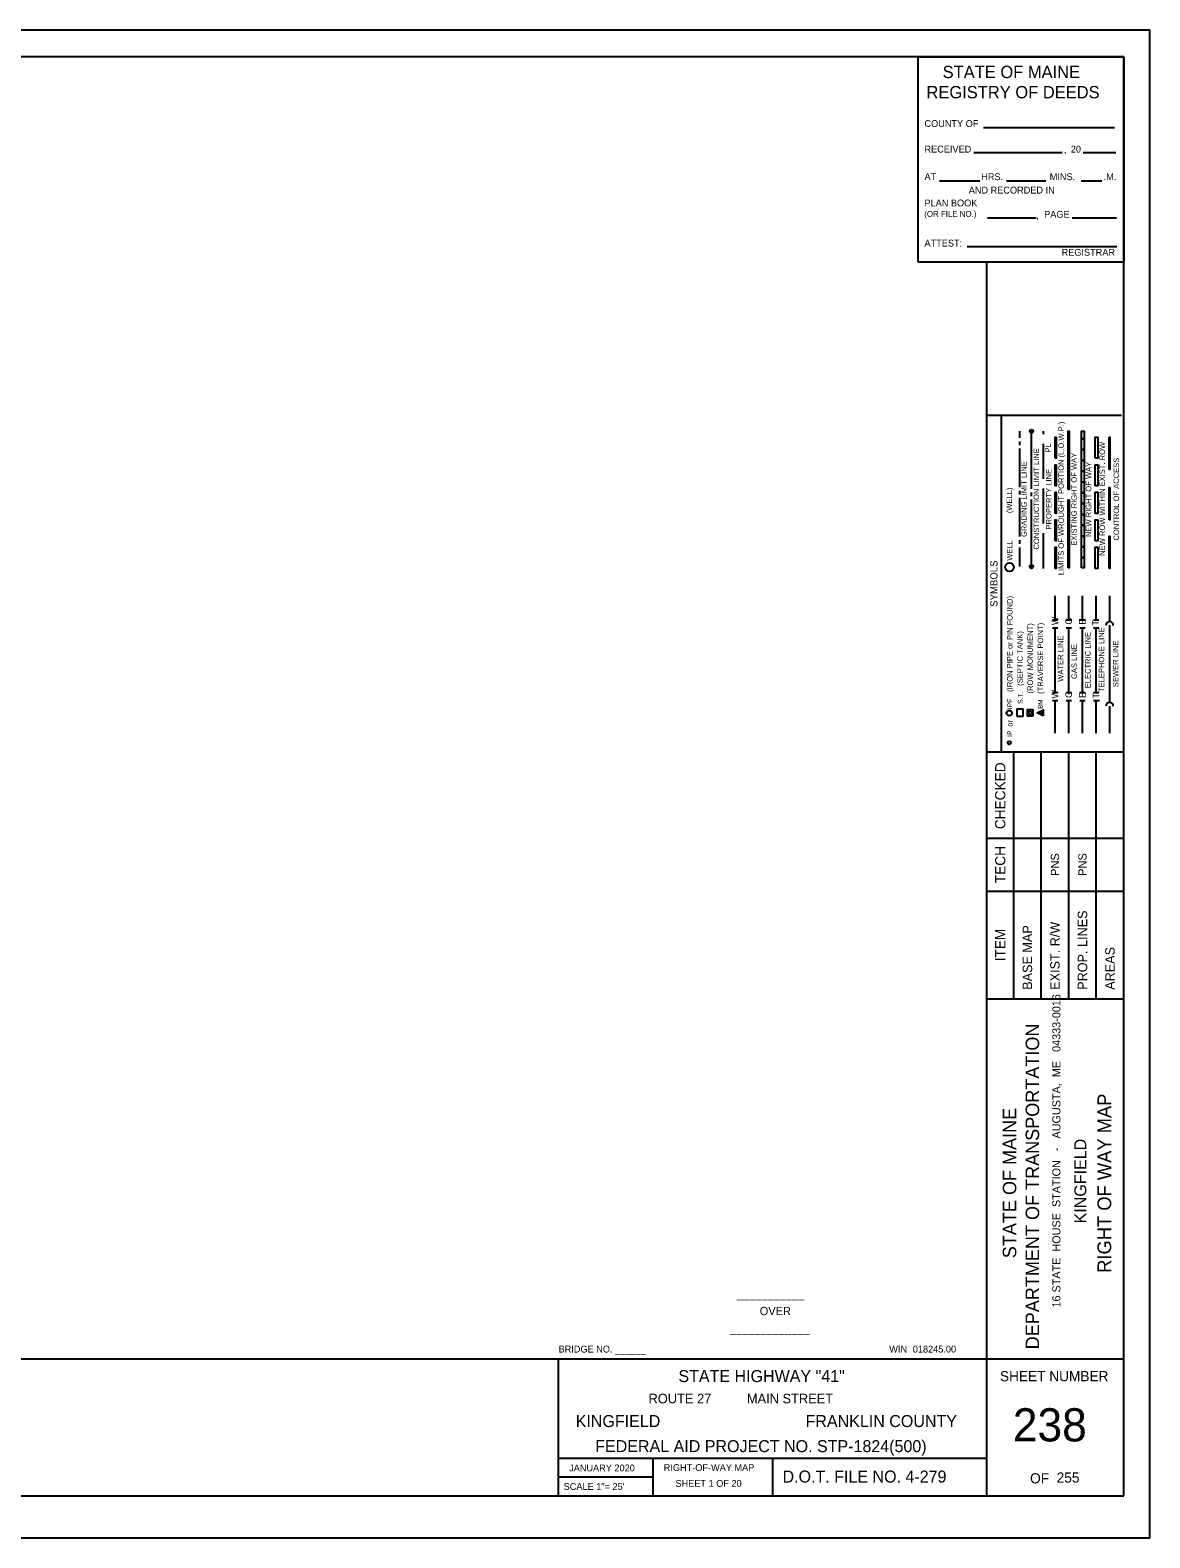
# Model space of a CAD drawing. Extents: x -415 to 435, y -303 to 247.
# Drawn here: x 26 to 435, y -303 to 247 of the extents above; entities that cross this region are included whole.
import ezdxf

# ---------------------------------------------------------------- set-up
doc = ezdxf.new("R2010")
doc.units = 0
for name, color, linetype in [('Border', 7, 'Continuous'), ('BRIDGE_TITLE', 7, 'Continuous'), ('HIGHWAY_TITLE', 7, 'Continuous'), ('PLOT BOUNDARY', 7, 'Continuous'), ('PRPTY SETUPS', 7, 'Continuous')]:
    doc.layers.add(name, color=color, linetype=linetype)

msp = doc.modelspace()

# ---------------------------------------------------------------- linework, layer by layer
at = {"layer": 'Border'}
for p, q in [((425, 237.5), (-375, 237.5)), ((425, -287.49), (425, 237.5)), ((375, -287.5), (375, 162.52)), ((375, 106.81), (424.21, 106.81)), ((380.25, 106.81), (380.25, -16.1)), ((387.03, 98.49), (387.03, 100.86)), ((391.35, 79.88), (391.35, 100.24)), ((395.67, 99.88), (395.67, 100.86)), ((387.03, 95.86), (387.03, 97.18)), ((387.03, 87.51), (387.03, 94.55)), ((395.67, 83.54), (395.67, 96.34)), ((387.03, 80.47), (387.03, 87.51)), ((387.03, 77.85), (387.03, 79.16)), ((391.35, 77.25), (391.35, 78.57)), ((395.67, 67.2), (395.67, 80)), ((387.03, 69.5), (387.03, 76.54)), ((391.35, 52.11), (391.35, 75.94)), ((387.03, 62.46), (387.03, 69.5)), ((387.03, 59.84), (387.03, 61.15)), ((395.67, 50.86), (395.67, 63.66)), ((387.03, 51.49), (387.03, 58.53)), ((399.99, 32.13), (399.99, 40.79)), ((404.97, 32.13), (404.97, 40.79)), ((409.94, 32.13), (409.94, 40.79)), ((414.92, 32.13), (414.92, 40.79)), ((419.9, 31.54), (419.9, 40.79)), ((399.01, 32.13), (400.98, 32.13)), ((399.01, 29.18), (400.98, 29.18)), ((399.99, 5.56), (399.99, 29.18)), ((403.98, 32.13), (405.95, 32.13)), ((403.98, 29.18), (405.95, 29.18)), ((404.97, 17.37), (404.97, 29.18)), ((408.96, 32.13), (410.93, 32.13)), ((408.96, 29.18), (410.93, 29.18)), ((409.94, 17.37), (409.94, 29.18)), ((413.94, 32.13), (415.9, 32.13)), ((413.94, 29.18), (415.9, 29.18)), ((414.92, 17.37), (414.92, 29.18)), ((419.9, 20.32), (419.9, 30.16)), ((404.97, 5.56), (404.97, 17.37)), ((409.94, 5.56), (409.94, 17.37)), ((414.92, 5.56), (414.92, 17.37)), ((419.9, 2.01), (419.9, 20.32)), ((399.01, 5.56), (400.98, 5.56)), ((403.98, 5.56), (405.95, 5.56)), ((408.96, 5.56), (410.93, 5.56)), ((413.94, 5.56), (415.9, 5.56)), ((399.01, 2.61), (400.98, 2.61)), ((399.99, -9.21), (399.99, 2.61)), ((403.98, 2.61), (405.95, 2.61)), ((404.97, -9.21), (404.97, 2.61)), ((408.96, 2.61), (410.93, 2.61)), ((409.94, -9.21), (409.94, 2.61)), ((413.94, 2.61), (416.1, 2.61)), ((414.92, -9.21), (414.92, 2.61)), ((419.9, -9.21), (419.9, 0.64)), ((375, -16.1), (425, -16.1)), ((384.84, -106.22), (384.84, -16.1)), ((394.88, -106.22), (394.88, -16.1)), ((404.92, -106.22), (404.92, -16.1)), ((414.96, -106.22), (414.96, -16.1)), ((375, -47.6), (425, -47.6)), ((375, -66.94), (425, -66.94)), ((375, -106.22), (425, -106.22)), ((-375, -237.49), (425, -237.49)), ((218.75, -287.5), (218.75, -237.49)), ((218.75, -273.75), (375, -273.75)), ((253.12, -273.75), (253.12, -287.5)), ((296.87, -273.75), (296.87, -287.5)), ((253.12, -280.62), (218.75, -280.62)), ((-375, -287.5), (425, -287.5))]:
    msp.add_line(p, q, dxfattribs=at)
for points in [[(404.71, 79.6), (404.71, 100.86), (405.1, 100.86), (405.1, 79.6)], [(409.62, 98.11), (409.62, 100.86), (410.6, 100.86), (410.6, 98.11)], [(399.99, 91.02), (399.99, 98.7), (400.39, 98.7), (400.39, 91.02)], [(409.62, 94.17), (409.62, 98.11), (410.6, 98.11), (410.6, 94.17)], [(409.62, 90.23), (409.62, 94.17), (410.6, 94.17), (410.6, 90.23)], [(414.59, 91.02), (414.59, 98.7), (415.58, 98.7), (415.58, 91.02)], [(419.7, 86.89), (419.7, 98.7), (419.9, 98.7), (419.9, 86.89)], [(399.99, 80.98), (399.99, 88.66), (400.39, 88.66), (400.39, 80.98)], [(409.62, 86.3), (409.62, 90.23), (410.6, 90.23), (410.6, 86.3)], [(414.59, 80.98), (414.59, 88.66), (415.58, 88.66), (415.58, 80.98)], [(409.62, 82.36), (409.62, 86.3), (410.6, 86.3), (410.6, 82.36)], [(399.99, 70.94), (399.99, 78.62), (400.39, 78.62), (400.39, 70.94)], [(409.62, 78.42), (409.62, 82.36), (410.6, 82.36), (410.6, 78.42)], [(409.62, 74.48), (409.62, 78.42), (410.6, 78.42), (410.6, 74.48)], [(414.59, 70.94), (414.59, 78.62), (415.58, 78.62), (415.58, 70.94)], [(419.7, 68.58), (419.7, 80.39), (419.9, 80.39), (419.9, 68.58)], [(404.71, 51.06), (404.71, 75.86), (405.1, 75.86), (405.1, 51.06)], [(409.62, 70.55), (409.62, 74.48), (410.6, 74.48), (410.6, 70.55)], [(399.99, 60.9), (399.99, 68.58), (400.39, 68.58), (400.39, 60.9)], [(409.62, 66.61), (409.62, 70.55), (410.6, 70.55), (410.6, 66.61)], [(409.62, 62.67), (409.62, 66.61), (410.6, 66.61), (410.6, 62.67)], [(414.59, 60.9), (414.59, 68.58), (415.58, 68.58), (415.58, 60.9)], [(409.62, 58.74), (409.62, 62.67), (410.6, 62.67), (410.6, 58.74)], [(419.7, 50.86), (419.7, 62.67), (419.9, 62.67), (419.9, 50.86)], [(399.99, 50.86), (399.99, 58.54), (400.39, 58.54), (400.39, 50.86)], [(409.62, 54.8), (409.62, 58.74), (410.6, 58.74), (410.6, 54.8)], [(414.59, 50.86), (414.59, 58.54), (415.58, 58.54), (415.58, 50.86)], [(409.62, 51.06), (409.62, 54.8), (410.6, 54.8), (410.6, 51.06)]]:
    msp.add_lwpolyline(points, close=True, dxfattribs=at)
for points in [[(385.95, -3.1), (388.31, -3.1), (388.31, -0.54), (385.95, -0.54), (385.95, -3.1)], [(391.98, -2.95), (391.98, -0.7), (389.73, -0.7), (389.73, -2.95), (391.98, -2.95)], [(395.54, -2.89), (393.44, -1.83), (395.54, -0.78), (395.54, -2.89)]]:
    msp.add_lwpolyline(points, dxfattribs=at)
for centre, radius in [((391.35, 100.86), 0.625), ((391.35, 100.86), 0.15), ((391.35, 100.86), 0.05), ((383.29, 51.3), 1.57), ((391.35, 51.49), 0.625), ((391.35, 51.49), 0.15), ((391.35, 51.49), 0.05), ((383.24, -1.91), 0.966), ((390.86, -1.82), 0.563), ((394.86, -1.82), 0.281), ((383.24, -12.74), 0.625)]:
    msp.add_circle(centre, radius, dxfattribs=at)
for centre in [(419.84, 30.08), (419.84, 0.56)]:
    msp.add_arc(centre, 1.35, 0, 180, dxfattribs=at)
at = {"layer": 'PLOT BOUNDARY'}
msp.add_lwpolyline([(-415.47, -302.8), (434.53, -302.8), (434.53, 247.2), (-415.47, 247.2)], close=True, dxfattribs=at)
at = {"layer": 'PRPTY SETUPS'}
for p, q in [((350.02, 237.5), (425, 237.5)), ((350.02, 162.52), (350.02, 237.5)), ((425, 237.5), (425, 162.52)), ((373.83, 211.74), (421.57, 211.74)), ((370.29, 202.57), (402.52, 202.57)), ((410.24, 202.57), (422.1, 202.57)), ((357.72, 192.29), (372.5, 192.29)), ((382.25, 192.29), (396.61, 192.29)), ((409.44, 192.29), (417, 192.29)), ((375.32, 178.78), (393.03, 178.78)), ((406.16, 178.78), (422.34, 178.78)), ((367.9, 168.33), (422.43, 168.33)), ((425, 162.52), (350.02, 162.52))]:
    msp.add_line(p, q, dxfattribs=at)

# ---------------------------------------------------------------- texts
at = {"layer": 'Border'}
for s, height, rotation, p in [('LIMITS OF WROUGHT PORTION (L.O.W.P.)', 1.9996, 90, (403.14, 48.4)), ('PL', 2, 90, (398.35, 93.09)), ('NEW ROW WITHIN EXIST. ROW', 1.9996, 90, (418.14, 55.45)), ('GRADING LIMIT LINE', 1.9996, 90, (389.59, 62.32)), ('CONSTRUCTION LIMIT LINE', 1.9996, 90, (394.11, 57.72)), ('EXISTING RIGHT OF WAY', 1.9996, 90, (407.86, 59.13)), ('NEW RIGHT OF WAY', 1.9996, 90, (413.16, 62.28)), ('CONTROL OF ACCESS', 1.9996, 90, (423.29, 61)), ('PROPERTY LINE', 1.9996, 90, (398.63, 65.04)), ('(WELL)', 2, 90, (384.23, 71.01)), ('WELL', 1.969, 90, (384.36, 53.66)), ('SYMBOLS', 2.614, 90, (378.93, 36.84)), ('(IRON PIPE or PIN FOUND)', 1.9996, 90, (384.41, 5.83)), ('W', 2.46, 90, (401.17, 30.16)), ('(ROW MONUMENT)', 1.9996, 90, (391.85, 5.23)), ('(TRAVERSE POINT)', 1.9996, 90, (395.58, 5.08)), ('G', 2.46, 90, (406.15, 30.36)), ('E', 2.46, 90, (411.13, 30.36)), ('T', 2.46, 90, (415.9, 29.97)), ('TELEPHONE LINE', 1.9996, 90, (417.87, 5.75)), ('(SEPTIC TANK)', 1.9996, 90, (388.13, 8.02)), ('WATER LINE', 2, 90, (402.95, 9.5)), ('GAS LINE', 2, 90, (407.92, 10.48)), ('ELECTRIC LINE', 1.9996, 90, (412.9, 7.13)), ('SEWER LINE', 2, 90, (423.05, 7.53)), ('W', 2.46, 90, (401.17, 3.39)), ('G', 2.46, 90, (406.15, 3.59)), ('E', 2.46, 90, (411.13, 3.59)), ('IPF', 1.749, 90, (384.28, -0.48)), ('S.T.', 1.749, 90, (388.12, 1.42)), ('BM', 1.641, 90, (395.4, -0.38)), ('T', 2.46, 90, (416.1, 3.39)), ('or', 2, 90, (384.47, -6.92)), ('IP', 1.749, 90, (384.28, -10.58)), ('CHECKED', 3.726, 90, (381.78, -44.27)), ('TECH', 3.726, 90, (381.78, -63.99)), ('PROP. LINES', 3.4449, 90, (411.66, -102.87)), ('ITEM', 3.726, 90, (381.78, -92.49)), ('BASE MAP', 3.445, 90, (391.58, -102.87)), ('EXIST. R/W', 3.445, 90, (401.62, -102.87)), ('AREAS', 3.445, 90, (421.7, -102.87)), ('16 STATE  HOUSE  STATION   -   AUGUSTA,  ME   04333-0016', 2.9528, 90, (401.89, -218.78)), ('DEPARTMENT OF TRANSPORTATION', 4.9217, 90, (394.13, -234.02)), ('RIGHT OF WAY MAP', 4.9996, 90, (420.42, -206.11)), ('STATE OF MAINE', 4.9217, 90, (385.79, -200.78)), ('D.O.T. FILE NO. 4-279', 4.375, 360, (300.49, -282.62))]:
    msp.add_text(s, height=height, rotation=rotation, dxfattribs=at).set_placement(p)
for s, height, p in [('SHEET NUMBER', 3.7264, (379.83, -245.67)), ('238', 12.097, (384.53, -267.62)), ('OF', 3.726, (390.83, -282.94)), ('255', 3.726, (400.54, -282.65))]:
    msp.add_text(s, height=height, dxfattribs=at).set_placement(p)
at = {"layer": 'BRIDGE_TITLE'}
for s, height, p in [('___________', 3, (283.84, -215.3)), ('OVER', 3, (292.18, -221.55)), ('_____________', 3, (281.29, -227.8)), ('BRIDGE NO. ______', 2.5, (218.75, -235.19))]:
    msp.add_text(s, height=height, dxfattribs=at).set_placement(p)
at = {"layer": 'HIGHWAY_TITLE'}
for s, height, rotation, p in [('PNS', 3, 90, (401.4, -61.3)), ('PNS', 3, 90, (411.44, -61.3)), ('KINGFIELD', 4.375, 90, (411.35, -188.1)), ('SCALE 1"= 25\'', 2.5, 360, (220.61, -285.31))]:
    msp.add_text(s, height=height, rotation=rotation, dxfattribs=at).set_placement(p)
for s, height, p in [('WIN', 2.5, (339.44, -235.19)), ('018245.00', 2.5, (348.02, -235.19)), ('STATE HIGHWAY "41"', 4.375, (262.49, -245.97)), ('ROUTE 27          MAIN STREET', 3.5, (251.59, -253.73)), ('KINGFIELD', 4.375, (225, -262.38)), ('FRANKLIN COUNTY', 4.375, (308.88, -262.38)), ('FEDERAL AID PROJECT NO. STP-1824(500)', 4.375, (232.12, -271.53)), ('JANUARY 2020', 2.5, (222.61, -278.55)), ('RIGHT-OF-WAY MAP', 2.5, (257.13, -278.43)), ('SHEET 1 OF 20', 2.5, (261.42, -284.18))]:
    msp.add_text(s, height=height, dxfattribs=at).set_placement(p)
at = {"layer": 'PRPTY SETUPS'}
for s, height, p in [('STATE OF MAINE', 4.5, (358.92, 229.71)), ('REGISTRY OF DEEDS', 4.5, (353.01, 222.33)), ('COUNTY OF', 2.5, (352.28, 211.89)), ('RECEIVED', 2.5, (352.28, 202.55)), ('20', 2.5, (405.68, 202.55)), (',', 2.61, (403.14, 202.33)), ('AT', 2.5, (352.28, 192.49)), ('HRS.', 2.5, (372.99, 192.49)), ('MINS.', 2.5, (398, 192.49)), ('.M.', 2.5, (417.67, 192.49)), ('AND RECORDED IN', 2.5, (368.43, 187.59)), ('PLAN BOOK ', 2.5, (352.28, 182.91)), ('(OR FILE NO.)', 2.1531, (352.21, 179.09)), (',', 2.61, (393.08, 178.45)), ('PAGE', 2.5, (395.95, 178.78)), ('ATTEST:', 2.5, (352.28, 168.27)), ('REGISTRAR', 2.5, (402.33, 164.91))]:
    msp.add_text(s, height=height, dxfattribs=at).set_placement(p)

doc.saveas('drawing.dxf')
